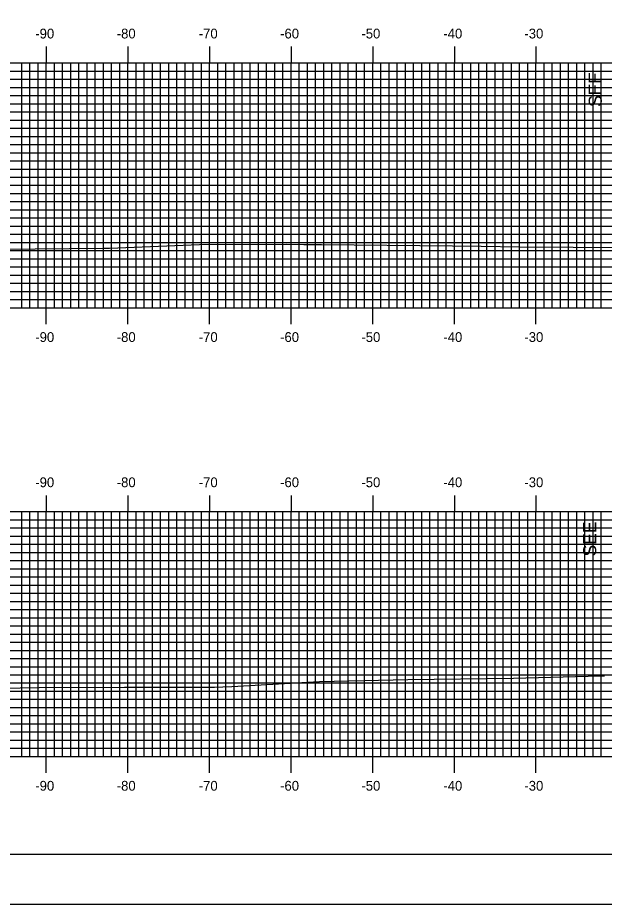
# Model space of a CAD drawing. Extents: x 2453 to 2796, y -1658 to -1438.
# Drawn here: x 2525.2 to 2597.1, y -1657.7 to -1549.1 of the extents above; entities that cross this region are included whole.
import ezdxf

# ---------------------------------------------------------------- set-up
doc = ezdxf.new("R2010")
doc.units = 0
for name, color, linetype in [('ANNOTATION', 7, 'Continuous'), ('BORDER', 7, 'Continuous'), ('H_V ANNOTATION', 7, 'Continuous'), ('MAJOR', 7, 'Continuous'), ('MINOR', 7, 'Continuous'), ('PLOT BOUNDARY', 7, 'Continuous'), ('S_Roadway_Centerline', 7, 'Continuous')]:
    doc.layers.add(name, color=color, linetype=linetype)

msp = doc.modelspace()

# ---------------------------------------------------------------- linework, layer by layer
at = {"layer": 'BORDER'}
msp.add_lwpolyline([(2469.1, -1651.6), (2789.1, -1651.6), (2789.1, -1441.6), (2469.1, -1441.6)], close=True, dxfattribs=at)
at = {"layer": 'MAJOR'}
for p, q in [((2528.7, -1552.6), (2528.7, -1554.6)), ((2538.7, -1552.6), (2538.7, -1554.6)), ((2548.7, -1552.6), (2548.7, -1554.6)), ((2558.7, -1552.6), (2558.7, -1554.6)), ((2568.7, -1552.6), (2568.7, -1554.6)), ((2578.7, -1552.6), (2578.7, -1554.6)), ((2588.7, -1552.6), (2588.7, -1554.6)), ((2478.7, -1554.6), (2758.7, -1554.6)), ((2478.7, -1554.6), (2758.7, -1554.6)), ((2528.7, -1584.6), (2528.7, -1554.6)), ((2538.7, -1584.6), (2538.7, -1554.6)), ((2548.7, -1584.6), (2548.7, -1554.6)), ((2558.7, -1584.6), (2558.7, -1554.6)), ((2568.7, -1584.6), (2568.7, -1554.6)), ((2578.7, -1584.6), (2578.7, -1554.6)), ((2588.7, -1584.6), (2588.7, -1554.6)), ((2478.7, -1559.6), (2758.7, -1559.6)), ((2478.7, -1564.6), (2758.7, -1564.6)), ((2478.7, -1569.6), (2758.7, -1569.6)), ((2478.7, -1574.6), (2758.7, -1574.6)), ((2478.7, -1579.6), (2758.7, -1579.6)), ((2478.7, -1584.6), (2758.7, -1584.6)), ((2478.7, -1584.6), (2758.7, -1584.6)), ((2528.7, -1586.61), (2528.7, -1584.6)), ((2538.7, -1586.61), (2538.7, -1584.6)), ((2548.7, -1586.61), (2548.7, -1584.6)), ((2558.7, -1586.61), (2558.7, -1584.6)), ((2568.7, -1586.61), (2568.7, -1584.6)), ((2578.7, -1586.61), (2578.7, -1584.6)), ((2588.7, -1586.61), (2588.7, -1584.6)), ((2528.7, -1607.6), (2528.7, -1609.6)), ((2538.7, -1607.6), (2538.7, -1609.6)), ((2548.7, -1607.6), (2548.7, -1609.6)), ((2558.7, -1607.6), (2558.7, -1609.6)), ((2568.7, -1607.6), (2568.7, -1609.6)), ((2578.7, -1607.6), (2578.7, -1609.6)), ((2588.7, -1607.6), (2588.7, -1609.6)), ((2478.7, -1609.6), (2758.7, -1609.6)), ((2478.7, -1609.6), (2758.7, -1609.6)), ((2528.7, -1639.6), (2528.7, -1609.6)), ((2538.7, -1639.6), (2538.7, -1609.6)), ((2548.7, -1639.6), (2548.7, -1609.6)), ((2558.7, -1639.6), (2558.7, -1609.6)), ((2568.7, -1639.6), (2568.7, -1609.6)), ((2578.7, -1639.6), (2578.7, -1609.6)), ((2588.7, -1639.6), (2588.7, -1609.6)), ((2478.7, -1614.6), (2758.7, -1614.6)), ((2478.7, -1619.6), (2758.7, -1619.6)), ((2478.7, -1624.6), (2758.7, -1624.6)), ((2478.7, -1629.6), (2758.7, -1629.6)), ((2478.7, -1634.6), (2758.7, -1634.6)), ((2478.7, -1639.6), (2758.7, -1639.6)), ((2478.7, -1639.6), (2758.7, -1639.6)), ((2528.7, -1641.61), (2528.7, -1639.6)), ((2538.7, -1641.61), (2538.7, -1639.6)), ((2548.7, -1641.61), (2548.7, -1639.6)), ((2558.7, -1641.61), (2558.7, -1639.6)), ((2568.7, -1641.61), (2568.7, -1639.6)), ((2578.7, -1641.61), (2578.7, -1639.6)), ((2588.7, -1641.61), (2588.7, -1639.6))]:
    msp.add_line(p, q, dxfattribs=at)
at = {"layer": 'MINOR'}
for p, q in [((2525.7, -1584.6), (2525.7, -1554.6)), ((2526.7, -1584.6), (2526.7, -1554.6)), ((2527.7, -1584.6), (2527.7, -1554.6)), ((2529.7, -1584.6), (2529.7, -1554.6)), ((2530.7, -1584.6), (2530.7, -1554.6)), ((2531.7, -1584.6), (2531.7, -1554.6)), ((2532.7, -1584.6), (2532.7, -1554.6)), ((2533.7, -1584.6), (2533.7, -1554.6)), ((2534.7, -1584.6), (2534.7, -1554.6)), ((2535.7, -1584.6), (2535.7, -1554.6)), ((2536.7, -1584.6), (2536.7, -1554.6)), ((2537.7, -1584.6), (2537.7, -1554.6)), ((2539.7, -1584.6), (2539.7, -1554.6)), ((2540.7, -1584.6), (2540.7, -1554.6)), ((2541.7, -1584.6), (2541.7, -1554.6)), ((2542.7, -1584.6), (2542.7, -1554.6)), ((2543.7, -1584.6), (2543.7, -1554.6)), ((2544.7, -1584.6), (2544.7, -1554.6)), ((2545.7, -1584.6), (2545.7, -1554.6)), ((2546.7, -1584.6), (2546.7, -1554.6)), ((2547.7, -1584.6), (2547.7, -1554.6)), ((2549.7, -1584.6), (2549.7, -1554.6)), ((2550.7, -1584.6), (2550.7, -1554.6)), ((2551.7, -1584.6), (2551.7, -1554.6)), ((2552.7, -1584.6), (2552.7, -1554.6)), ((2553.7, -1584.6), (2553.7, -1554.6)), ((2554.7, -1584.6), (2554.7, -1554.6)), ((2555.7, -1584.6), (2555.7, -1554.6)), ((2556.7, -1584.6), (2556.7, -1554.6)), ((2557.7, -1584.6), (2557.7, -1554.6)), ((2559.7, -1584.6), (2559.7, -1554.6)), ((2560.7, -1584.6), (2560.7, -1554.6)), ((2561.7, -1584.6), (2561.7, -1554.6)), ((2562.7, -1584.6), (2562.7, -1554.6)), ((2563.7, -1584.6), (2563.7, -1554.6)), ((2564.7, -1584.6), (2564.7, -1554.6)), ((2565.7, -1584.6), (2565.7, -1554.6)), ((2566.7, -1584.6), (2566.7, -1554.6)), ((2567.7, -1584.6), (2567.7, -1554.6)), ((2569.7, -1584.6), (2569.7, -1554.6)), ((2570.7, -1584.6), (2570.7, -1554.6)), ((2571.7, -1584.6), (2571.7, -1554.6)), ((2572.7, -1584.6), (2572.7, -1554.6)), ((2573.7, -1584.6), (2573.7, -1554.6)), ((2574.7, -1584.6), (2574.7, -1554.6)), ((2575.7, -1584.6), (2575.7, -1554.6)), ((2576.7, -1584.6), (2576.7, -1554.6)), ((2577.7, -1584.6), (2577.7, -1554.6)), ((2579.7, -1584.6), (2579.7, -1554.6)), ((2580.7, -1584.6), (2580.7, -1554.6)), ((2581.7, -1584.6), (2581.7, -1554.6)), ((2582.7, -1584.6), (2582.7, -1554.6)), ((2583.7, -1584.6), (2583.7, -1554.6)), ((2584.7, -1584.6), (2584.7, -1554.6)), ((2585.7, -1584.6), (2585.7, -1554.6)), ((2586.7, -1584.6), (2586.7, -1554.6)), ((2587.7, -1584.6), (2587.7, -1554.6)), ((2589.7, -1584.6), (2589.7, -1554.6)), ((2590.7, -1584.6), (2590.7, -1554.6)), ((2591.7, -1584.6), (2591.7, -1554.6)), ((2592.7, -1584.6), (2592.7, -1554.6)), ((2593.7, -1584.6), (2593.7, -1554.6)), ((2594.7, -1584.6), (2594.7, -1554.6)), ((2595.7, -1584.6), (2595.7, -1554.6)), ((2596.7, -1584.6), (2596.7, -1554.6)), ((2478.7, -1555.6), (2758.7, -1555.6)), ((2478.7, -1556.6), (2758.7, -1556.6)), ((2478.7, -1557.6), (2758.7, -1557.6)), ((2478.7, -1558.6), (2758.7, -1558.6)), ((2478.7, -1560.6), (2758.7, -1560.6)), ((2478.7, -1561.6), (2758.7, -1561.6)), ((2478.7, -1562.6), (2758.7, -1562.6)), ((2478.7, -1563.6), (2758.7, -1563.6)), ((2478.7, -1565.6), (2758.7, -1565.6)), ((2478.7, -1566.6), (2758.7, -1566.6)), ((2478.7, -1567.6), (2758.7, -1567.6)), ((2478.7, -1568.6), (2758.7, -1568.6)), ((2478.7, -1570.6), (2758.7, -1570.6)), ((2478.7, -1571.6), (2758.7, -1571.6)), ((2478.7, -1572.6), (2758.7, -1572.6)), ((2478.7, -1573.6), (2758.7, -1573.6)), ((2478.7, -1575.6), (2758.7, -1575.6)), ((2478.7, -1576.6), (2758.7, -1576.6)), ((2478.7, -1577.6), (2758.7, -1577.6)), ((2478.7, -1578.6), (2758.7, -1578.6)), ((2478.7, -1580.6), (2758.7, -1580.6)), ((2478.7, -1581.6), (2758.7, -1581.6)), ((2478.7, -1582.6), (2758.7, -1582.6)), ((2478.7, -1583.6), (2758.7, -1583.6)), ((2525.7, -1639.6), (2525.7, -1609.6)), ((2526.7, -1639.6), (2526.7, -1609.6)), ((2527.7, -1639.6), (2527.7, -1609.6)), ((2529.7, -1639.6), (2529.7, -1609.6)), ((2530.7, -1639.6), (2530.7, -1609.6)), ((2531.7, -1639.6), (2531.7, -1609.6)), ((2532.7, -1639.6), (2532.7, -1609.6)), ((2533.7, -1639.6), (2533.7, -1609.6)), ((2534.7, -1639.6), (2534.7, -1609.6)), ((2535.7, -1639.6), (2535.7, -1609.6)), ((2536.7, -1639.6), (2536.7, -1609.6)), ((2537.7, -1639.6), (2537.7, -1609.6)), ((2539.7, -1639.6), (2539.7, -1609.6)), ((2540.7, -1639.6), (2540.7, -1609.6)), ((2541.7, -1639.6), (2541.7, -1609.6)), ((2542.7, -1639.6), (2542.7, -1609.6)), ((2543.7, -1639.6), (2543.7, -1609.6)), ((2544.7, -1639.6), (2544.7, -1609.6)), ((2545.7, -1639.6), (2545.7, -1609.6)), ((2546.7, -1639.6), (2546.7, -1609.6)), ((2547.7, -1639.6), (2547.7, -1609.6)), ((2549.7, -1639.6), (2549.7, -1609.6)), ((2550.7, -1639.6), (2550.7, -1609.6)), ((2551.7, -1639.6), (2551.7, -1609.6)), ((2552.7, -1639.6), (2552.7, -1609.6)), ((2553.7, -1639.6), (2553.7, -1609.6)), ((2554.7, -1639.6), (2554.7, -1609.6)), ((2555.7, -1639.6), (2555.7, -1609.6)), ((2556.7, -1639.6), (2556.7, -1609.6)), ((2557.7, -1639.6), (2557.7, -1609.6)), ((2559.7, -1639.6), (2559.7, -1609.6)), ((2560.7, -1639.6), (2560.7, -1609.6)), ((2561.7, -1639.6), (2561.7, -1609.6)), ((2562.7, -1639.6), (2562.7, -1609.6)), ((2563.7, -1639.6), (2563.7, -1609.6)), ((2564.7, -1639.6), (2564.7, -1609.6)), ((2565.7, -1639.6), (2565.7, -1609.6)), ((2566.7, -1639.6), (2566.7, -1609.6)), ((2567.7, -1639.6), (2567.7, -1609.6)), ((2569.7, -1639.6), (2569.7, -1609.6)), ((2570.7, -1639.6), (2570.7, -1609.6)), ((2571.7, -1639.6), (2571.7, -1609.6)), ((2572.7, -1639.6), (2572.7, -1609.6)), ((2573.7, -1639.6), (2573.7, -1609.6)), ((2574.7, -1639.6), (2574.7, -1609.6)), ((2575.7, -1639.6), (2575.7, -1609.6)), ((2576.7, -1639.6), (2576.7, -1609.6)), ((2577.7, -1639.6), (2577.7, -1609.6)), ((2579.7, -1639.6), (2579.7, -1609.6)), ((2580.7, -1639.6), (2580.7, -1609.6)), ((2581.7, -1639.6), (2581.7, -1609.6)), ((2582.7, -1639.6), (2582.7, -1609.6)), ((2583.7, -1639.6), (2583.7, -1609.6)), ((2584.7, -1639.6), (2584.7, -1609.6)), ((2585.7, -1639.6), (2585.7, -1609.6)), ((2586.7, -1639.6), (2586.7, -1609.6)), ((2587.7, -1639.6), (2587.7, -1609.6)), ((2589.7, -1639.6), (2589.7, -1609.6)), ((2590.7, -1639.6), (2590.7, -1609.6)), ((2591.7, -1639.6), (2591.7, -1609.6)), ((2592.7, -1639.6), (2592.7, -1609.6)), ((2593.7, -1639.6), (2593.7, -1609.6)), ((2594.7, -1639.6), (2594.7, -1609.6)), ((2595.7, -1639.6), (2595.7, -1609.6)), ((2596.7, -1639.6), (2596.7, -1609.6)), ((2478.7, -1610.6), (2758.7, -1610.6)), ((2478.7, -1611.6), (2758.7, -1611.6)), ((2478.7, -1612.6), (2758.7, -1612.6)), ((2478.7, -1613.6), (2758.7, -1613.6)), ((2478.7, -1615.6), (2758.7, -1615.6)), ((2478.7, -1616.6), (2758.7, -1616.6)), ((2478.7, -1617.6), (2758.7, -1617.6)), ((2478.7, -1618.6), (2758.7, -1618.6)), ((2478.7, -1620.6), (2758.7, -1620.6)), ((2478.7, -1621.6), (2758.7, -1621.6)), ((2478.7, -1622.6), (2758.7, -1622.6)), ((2478.7, -1623.6), (2758.7, -1623.6)), ((2478.7, -1625.6), (2758.7, -1625.6)), ((2478.7, -1626.6), (2758.7, -1626.6)), ((2478.7, -1627.6), (2758.7, -1627.6)), ((2478.7, -1628.6), (2758.7, -1628.6)), ((2478.7, -1630.6), (2758.7, -1630.6)), ((2478.7, -1631.6), (2758.7, -1631.6)), ((2478.7, -1632.6), (2758.7, -1632.6)), ((2478.7, -1633.6), (2758.7, -1633.6)), ((2478.7, -1635.6), (2758.7, -1635.6)), ((2478.7, -1636.6), (2758.7, -1636.6)), ((2478.7, -1637.6), (2758.7, -1637.6)), ((2478.7, -1638.6), (2758.7, -1638.6))]:
    msp.add_line(p, q, dxfattribs=at)
at = {"layer": 'PLOT BOUNDARY'}
msp.add_lwpolyline([(2452.91, -1657.72), (2792.91, -1657.72), (2792.91, -1437.72), (2452.91, -1437.72)], close=True, dxfattribs=at)
at = {"layer": 'S_Roadway_Centerline'}
for points in [[(2478.7, -1578.07), (2483.61, -1577.88), (2489.03, -1577.79), (2493.33, -1577.67), (2501.63, -1577.8), (2510.08, -1577.55), (2512.57, -1577.5), (2514.74, -1577.5), (2535.7, -1577.31), (2536.46, -1577.31), (2547.46, -1576.85), (2558.14, -1576.82), (2560.25, -1576.87), (2562.41, -1576.87), (2578.48, -1577.01), (2581.98, -1577.05), (2586.67, -1577.12), (2606.39, -1577.25)], [(2478.7, -1631.71), (2481.71, -1631.64), (2482.19, -1631.63), (2482.64, -1631.61), (2503.71, -1631.68), (2506.22, -1631.7), (2525.49, -1631.19), (2527.81, -1631.16), (2538.29, -1631.12), (2549.31, -1631.11), (2550.35, -1631.09), (2551.43, -1631.05), (2562.17, -1630.42), (2573.02, -1630.17), (2585.95, -1630.01), (2596.6, -1629.72), (2597.11, -1629.73)]]:
    msp.add_lwpolyline(points, dxfattribs=at)

# ---------------------------------------------------------------- texts
at = {"layer": 'ANNOTATION'}
for p in [(2596.76, -1559.99), (2596.08, -1615.09)]:
    msp.add_text('SEE', height=1.6, rotation=90, dxfattribs=at).set_placement(p)
at = {"layer": 'H_V ANNOTATION'}
for s, p in [('-90', (2527.35, -1551.6)), ('-80', (2537.33, -1551.6)), ('-70', (2547.38, -1551.6)), ('-60', (2557.35, -1551.6)), ('-50', (2567.31, -1551.6)), ('-40', (2577.35, -1551.6)), ('-30', (2587.28, -1551.6)), ('-90', (2527.35, -1588.8)), ('-80', (2537.33, -1588.8)), ('-70', (2547.38, -1588.8)), ('-60', (2557.35, -1588.8)), ('-50', (2567.31, -1588.8)), ('-40', (2577.35, -1588.8)), ('-30', (2587.28, -1588.8)), ('-90', (2527.35, -1606.6)), ('-80', (2537.33, -1606.6)), ('-70', (2547.38, -1606.6)), ('-60', (2557.35, -1606.6)), ('-50', (2567.31, -1606.6)), ('-40', (2577.35, -1606.6)), ('-30', (2587.28, -1606.6)), ('-90', (2527.35, -1643.8)), ('-80', (2537.33, -1643.8)), ('-70', (2547.38, -1643.8)), ('-60', (2557.35, -1643.8)), ('-50', (2567.31, -1643.8)), ('-40', (2577.35, -1643.8)), ('-30', (2587.28, -1643.8))]:
    msp.add_text(s, height=1.2, dxfattribs=at).set_placement(p)

doc.saveas('drawing.dxf')
